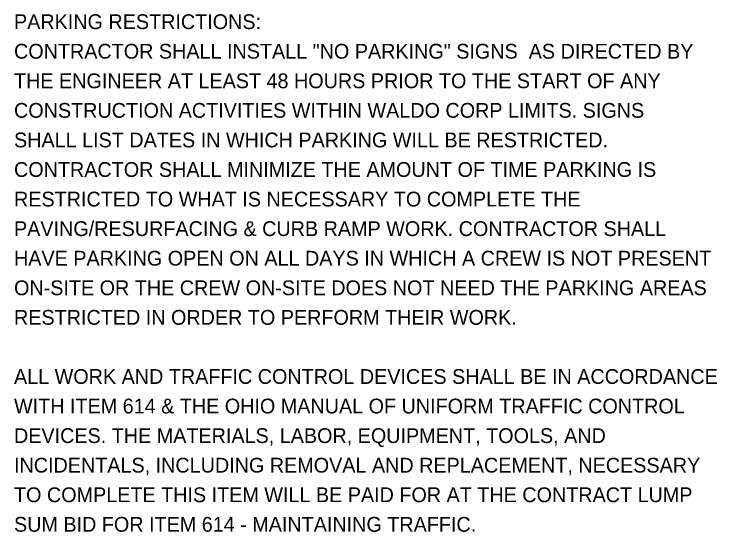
# Model space of a CAD drawing. Extents: x 37613.4 to 37668.4, y 18853.7 to 18946.8.
# Drawn here: x 37613.42 to 37620.08, y 18903.89 to 18908.8 of the extents above; entities that cross this region are included whole.
import ezdxf

# ---------------------------------------------------------------- set-up
doc = ezdxf.new("R2010")
doc.units = 0
doc.layers.add('SH_Text', color=7, linetype='Continuous')

msp = doc.modelspace()

# ---------------------------------------------------------------- texts
at = {"layer": 'SH_Text'}
for s, p in [('PARKING RESTRICTIONS:', (37613.4194, 18908.6544)), ('CONTRACTOR SHALL INSTALL "NO PARKING" SIGNS  AS DIRECTED BY ', (37613.4194, 18908.3744)), ('THE ENGINEER AT LEAST 48 HOURS PRIOR TO THE START OF ANY ', (37613.4194, 18908.0944)), ('CONSTRUCTION ACTIVITIES WITHIN WALDO CORP LIMITS. SIGNS ', (37613.4194, 18907.8144)), ('SHALL LIST DATES IN WHICH PARKING WILL BE RESTRICTED. ', (37613.4194, 18907.5344)), ('CONTRACTOR SHALL MINIMIZE THE AMOUNT OF TIME PARKING IS ', (37613.4194, 18907.2544)), ('RESTRICTED TO WHAT IS NECESSARY TO COMPLETE THE ', (37613.4194, 18906.9744)), ('PAVING/RESURFACING & CURB RAMP WORK. CONTRACTOR SHALL ', (37613.4194, 18906.6944)), ('HAVE PARKING OPEN ON ALL DAYS IN WHICH A CREW IS NOT PRESENT ', (37613.4194, 18906.4144)), ('ON-SITE OR THE CREW ON-SITE DOES NOT NEED THE PARKING AREAS ', (37613.4194, 18906.1344)), ('RESTRICTED IN ORDER TO PERFORM THEIR WORK.', (37613.4194, 18905.8544)), ('ALL WORK AND TRAFFIC CONTROL DEVICES SHALL BE IN ACCORDANCE ', (37613.4194, 18905.2944)), ('WITH ITEM 614 & THE OHIO MANUAL OF UNIFORM TRAFFIC CONTROL ', (37613.4194, 18905.0144)), ('DEVICES. THE MATERIALS, LABOR, EQUIPMENT, TOOLS, AND ', (37613.4194, 18904.7344)), ('INCIDENTALS, INCLUDING REMOVAL AND REPLACEMENT, NECESSARY ', (37613.4194, 18904.4544)), ('TO COMPLETE THIS ITEM WILL BE PAID FOR AT THE CONTRACT LUMP ', (37613.4194, 18904.1744)), ('SUM BID FOR ITEM 614 - MAINTAINING TRAFFIC.', (37613.4194, 18903.8944))]:
    msp.add_text(s, height=0.14, dxfattribs=at).set_placement(p)

doc.saveas('drawing.dxf')
